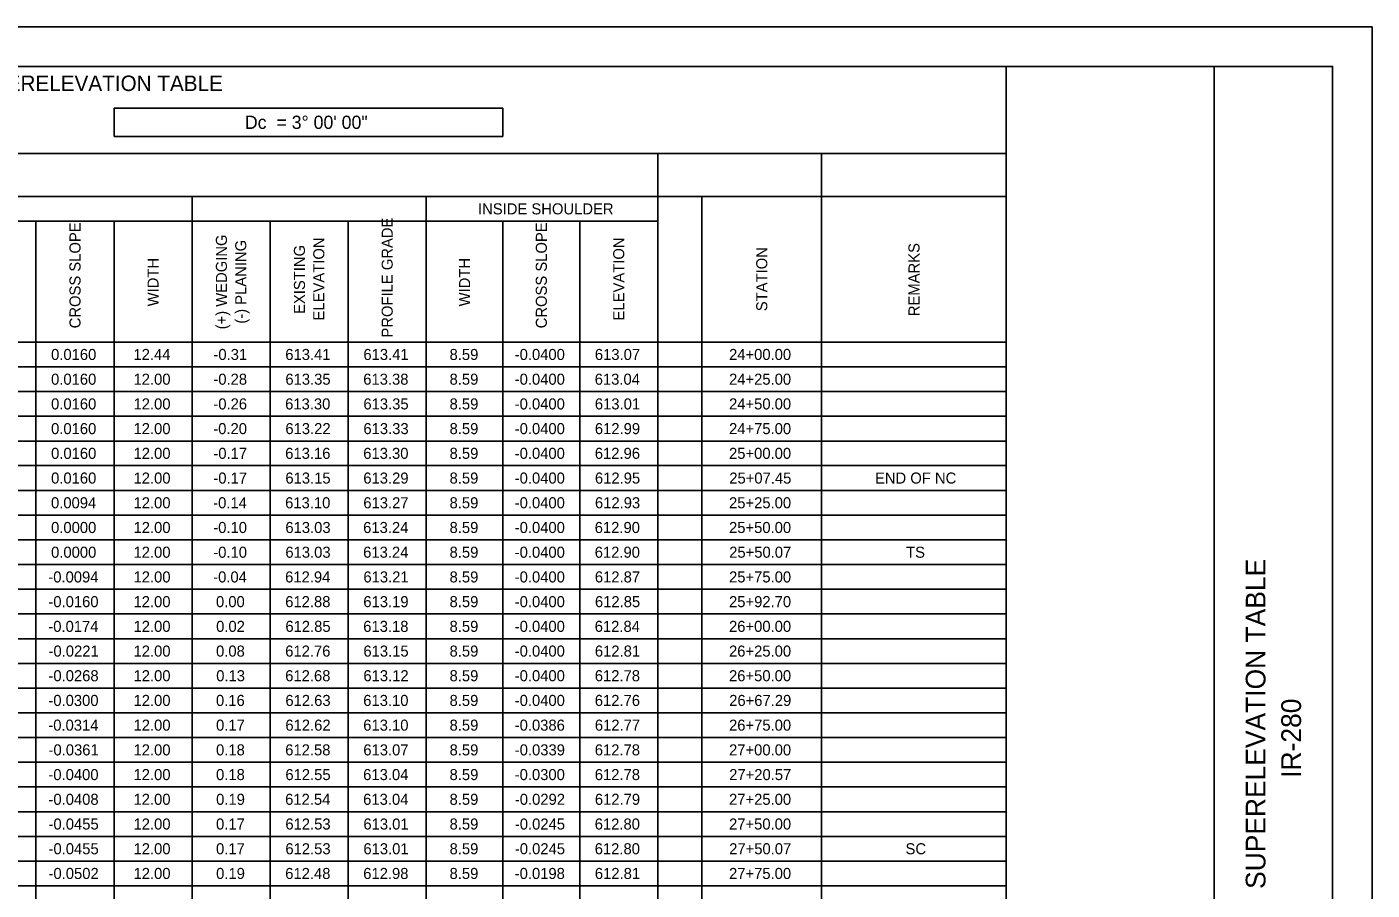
# Model space of a CAD drawing. Extents: x 0 to 34, y 0 to 22.
# Drawn here: x 16.97 to 34, y 11.07 to 22 of the extents above; entities that cross this region are included whole.
import ezdxf

# ---------------------------------------------------------------- set-up
doc = ezdxf.new("R2010")
doc.units = 0
for name, color, linetype in [('SH_Border', 7, 'Continuous'), ('SH_Cut_Line', 7, 'Continuous'), ('SH_Data', 7, 'Continuous'), ('SH_Text', 7, 'Continuous')]:
    doc.layers.add(name, color=color, linetype=linetype)

msp = doc.modelspace()

# ---------------------------------------------------------------- linework, layer by layer
at = {"layer": 'SH_Border'}
msp.add_line((32, 0.5), (32, 21.5), dxfattribs=at)
msp.add_lwpolyline([(1.5, 21.5), (33.5, 21.5), (33.5, 0.5), (1.5, 0.5)], close=True, dxfattribs=at)
at = {"layer": 'SH_Cut_Line'}
msp.add_lwpolyline([(0, 0), (34, 0), (34, 22), (0, 22)], close=True, dxfattribs=at)
at = {"layer": 'SH_Text'}
for p, q in [((5.189, 21.5), (29.368, 21.5)), ((29.368, 21.5), (29.368, 0.484)), ((18.069, 20.973), (22.994, 20.973)), ((18.069, 20.973), (18.069, 20.611)), ((22.994, 20.973), (22.994, 20.611)), ((18.069, 20.611), (22.994, 20.611)), ((4.135, 20.396), (29.368, 20.396)), ((24.954, 20.396), (24.954, 0.484)), ((27.029, 20.396), (27.029, 0.484)), ((4.135, 19.853), (29.368, 19.853)), ((19.057, 19.853), (19.057, 0.484)), ((22.022, 19.853), (22.022, 0.484)), ((25.514, 19.853), (25.514, 0.484)), ((4.135, 19.54), (24.954, 19.54)), ((17.081, 19.54), (17.081, 0.484)), ((18.069, 19.54), (18.069, 0.484)), ((20.046, 19.54), (20.046, 0.484)), ((21.034, 19.54), (21.034, 0.484)), ((22.994, 19.54), (22.994, 0.484)), ((23.966, 19.54), (23.966, 0.484)), ((4.135, 18.008), (29.368, 18.008)), ((4.135, 17.695), (29.368, 17.695)), ((4.135, 17.382), (29.368, 17.382)), ((4.135, 17.069), (29.368, 17.069)), ((4.135, 16.756), (29.368, 16.756)), ((4.135, 16.444), (29.368, 16.444)), ((4.135, 16.131), (29.368, 16.131)), ((4.135, 15.818), (29.368, 15.818)), ((4.135, 15.505), (29.368, 15.505)), ((4.135, 15.192), (29.368, 15.192)), ((4.135, 14.879), (29.368, 14.879)), ((4.135, 14.566), (29.368, 14.566)), ((4.135, 14.253), (29.368, 14.253)), ((4.135, 13.94), (29.368, 13.94)), ((4.135, 13.627), (29.368, 13.627)), ((4.135, 13.314), (29.368, 13.314)), ((4.135, 13.001), (29.368, 13.001)), ((4.135, 12.688), (29.368, 12.688)), ((4.135, 12.375), (29.368, 12.375)), ((4.135, 12.062), (29.368, 12.062)), ((4.135, 11.749), (29.368, 11.749)), ((4.135, 11.436), (29.368, 11.436)), ((4.135, 11.124), (29.368, 11.124))]:
    msp.add_line(p, q, dxfattribs=at)

# ---------------------------------------------------------------- texts
at = {"layer": 'SH_Data'}
for s, p in [('SUPERELEVATION TABLE', (32.65, 11.084)), ('IR-280', (33.1, 12.491))]:
    msp.add_text(s, height=0.25, rotation=90, dxfattribs=at).set_placement(p)
at = {"layer": 'SH_Text'}
for s, height, p in [('WOO/LUC-280-06.20/00.00 - SUPERELEVATION TABLE', 0.196, (12.689, 21.188)), ('Dc  = 3° 00\' 00"', 0.168, (19.726, 20.708)), ('INSIDE SHOULDER', 0.14, (22.678, 19.626)), ('0.0160', 0.14, (17.272, 17.782)), ('12.44', 0.14, (18.315, 17.782)), ('-0.31', 0.14, (19.328, 17.782)), ('613.41', 0.14, (20.238, 17.782)), ('613.41', 0.14, (21.227, 17.782)), ('8.59', 0.14, (22.318, 17.782)), ('-0.0400', 0.14, (23.143, 17.782)), ('613.07', 0.14, (24.158, 17.782)), ('24+00.00', 0.14, (25.857, 17.782)), ('0.0160', 0.14, (17.272, 17.469)), ('12.00', 0.14, (18.316, 17.469)), ('-0.28', 0.14, (19.327, 17.469)), ('613.35', 0.14, (20.239, 17.469)), ('613.38', 0.14, (21.225, 17.469)), ('8.59', 0.14, (22.318, 17.469)), ('-0.0400', 0.14, (23.143, 17.469)), ('613.04', 0.14, (24.156, 17.469)), ('24+25.00', 0.14, (25.857, 17.469)), ('0.0160', 0.14, (17.272, 17.156)), ('12.00', 0.14, (18.316, 17.156)), ('-0.26', 0.14, (19.327, 17.156)), ('613.30', 0.14, (20.236, 17.156)), ('613.35', 0.14, (21.227, 17.156)), ('8.59', 0.14, (22.318, 17.156)), ('-0.0400', 0.14, (23.143, 17.156)), ('613.01', 0.14, (24.158, 17.156)), ('24+50.00', 0.14, (25.857, 17.156)), ('0.0160', 0.14, (17.272, 16.843)), ('12.00', 0.14, (18.316, 16.843)), ('-0.20', 0.14, (19.326, 16.843)), ('613.22', 0.14, (20.239, 16.843)), ('613.33', 0.14, (21.227, 16.843)), ('8.59', 0.14, (22.318, 16.843)), ('-0.0400', 0.14, (23.143, 16.843)), ('612.99', 0.14, (24.158, 16.843)), ('24+75.00', 0.14, (25.857, 16.843)), ('0.0160', 0.14, (17.272, 16.53)), ('12.00', 0.14, (18.316, 16.53)), ('-0.17', 0.14, (19.327, 16.53)), ('613.16', 0.14, (20.237, 16.53)), ('613.30', 0.14, (21.225, 16.53)), ('8.59', 0.14, (22.318, 16.53)), ('-0.0400', 0.14, (23.143, 16.53)), ('612.96', 0.14, (24.157, 16.53)), ('25+00.00', 0.14, (25.857, 16.53)), ('0.0160', 0.14, (17.272, 16.217)), ('12.00', 0.14, (18.316, 16.217)), ('-0.17', 0.14, (19.327, 16.217)), ('613.15', 0.14, (20.239, 16.217)), ('613.29', 0.14, (21.226, 16.217)), ('8.59', 0.14, (22.318, 16.217)), ('-0.0400', 0.14, (23.143, 16.217)), ('612.95', 0.14, (24.159, 16.217)), ('25+07.45', 0.14, (25.86, 16.217)), ('END OF NC', 0.14, (27.705, 16.217)), ('0.0094', 0.14, (17.271, 15.904)), ('12.00', 0.14, (18.316, 15.904)), ('-0.14', 0.14, (19.325, 15.904)), ('613.10', 0.14, (20.236, 15.904)), ('613.27', 0.14, (21.226, 15.904)), ('8.59', 0.14, (22.318, 15.904)), ('-0.0400', 0.14, (23.143, 15.904)), ('612.93', 0.14, (24.159, 15.904)), ('25+25.00', 0.14, (25.857, 15.904)), ('0.0000', 0.14, (17.272, 15.591)), ('12.00', 0.14, (18.316, 15.591)), ('-0.10', 0.14, (19.326, 15.591)), ('613.03', 0.14, (20.239, 15.591)), ('613.24', 0.14, (21.224, 15.591)), ('8.59', 0.14, (22.318, 15.591)), ('-0.0400', 0.14, (23.143, 15.591)), ('612.90', 0.14, (24.156, 15.591)), ('25+50.00', 0.14, (25.857, 15.591)), ('0.0000', 0.14, (17.272, 15.278)), ('12.00', 0.14, (18.316, 15.278)), ('-0.10', 0.14, (19.326, 15.278)), ('613.03', 0.14, (20.239, 15.278)), ('613.24', 0.14, (21.224, 15.278)), ('8.59', 0.14, (22.318, 15.278)), ('-0.0400', 0.14, (23.143, 15.278)), ('612.90', 0.14, (24.156, 15.278)), ('25+50.07', 0.14, (25.859, 15.278)), ('TS', 0.14, (28.099, 15.278)), ('-0.0094', 0.14, (17.237, 14.965)), ('12.00', 0.14, (18.316, 14.965)), ('-0.04', 0.14, (19.325, 14.965)), ('612.94', 0.14, (20.236, 14.965)), ('613.21', 0.14, (21.227, 14.965)), ('8.59', 0.14, (22.318, 14.965)), ('-0.0400', 0.14, (23.143, 14.965)), ('612.87', 0.14, (24.158, 14.965)), ('25+75.00', 0.14, (25.857, 14.965)), ('-0.0160', 0.14, (17.238, 14.652)), ('12.00', 0.14, (18.316, 14.652)), ('0.00', 0.14, (19.36, 14.652)), ('612.88', 0.14, (20.237, 14.652)), ('613.19', 0.14, (21.226, 14.652)), ('8.59', 0.14, (22.318, 14.652)), ('-0.0400', 0.14, (23.143, 14.652)), ('612.85', 0.14, (24.159, 14.652)), ('25+92.70', 0.14, (25.857, 14.652)), ('-0.0174', 0.14, (17.237, 14.339)), ('12.00', 0.14, (18.316, 14.339)), ('0.02', 0.14, (19.362, 14.339)), ('612.85', 0.14, (20.239, 14.339)), ('613.18', 0.14, (21.225, 14.339)), ('8.59', 0.14, (22.318, 14.339)), ('-0.0400', 0.14, (23.143, 14.339)), ('612.84', 0.14, (24.156, 14.339)), ('26+00.00', 0.14, (25.857, 14.339)), ('-0.0221', 0.14, (17.24, 14.026)), ('12.00', 0.14, (18.316, 14.026)), ('0.08', 0.14, (19.361, 14.026)), ('612.76', 0.14, (20.237, 14.026)), ('613.15', 0.14, (21.227, 14.026)), ('8.59', 0.14, (22.318, 14.026)), ('-0.0400', 0.14, (23.143, 14.026)), ('612.81', 0.14, (24.158, 14.026)), ('26+25.00', 0.14, (25.857, 14.026)), ('-0.0268', 0.14, (17.239, 13.714)), ('12.00', 0.14, (18.316, 13.714)), ('0.13', 0.14, (19.363, 13.714)), ('612.68', 0.14, (20.237, 13.714)), ('613.12', 0.14, (21.227, 13.714)), ('8.59', 0.14, (22.318, 13.714)), ('-0.0400', 0.14, (23.143, 13.714)), ('612.78', 0.14, (24.157, 13.714)), ('26+50.00', 0.14, (25.857, 13.714)), ('-0.0300', 0.14, (17.238, 13.401)), ('12.00', 0.14, (18.316, 13.401)), ('0.16', 0.14, (19.36, 13.401)), ('612.63', 0.14, (20.239, 13.401)), ('613.10', 0.14, (21.225, 13.401)), ('8.59', 0.14, (22.318, 13.401)), ('-0.0400', 0.14, (23.143, 13.401)), ('612.76', 0.14, (24.157, 13.401)), ('26+67.29', 0.14, (25.859, 13.401)), ('-0.0314', 0.14, (17.237, 13.088)), ('12.00', 0.14, (18.316, 13.088)), ('0.17', 0.14, (19.361, 13.088)), ('612.62', 0.14, (20.239, 13.088)), ('613.10', 0.14, (21.225, 13.088)), ('8.59', 0.14, (22.318, 13.088)), ('-0.0386', 0.14, (23.143, 13.088)), ('612.77', 0.14, (24.158, 13.088)), ('26+75.00', 0.14, (25.857, 13.088)), ('-0.0361', 0.14, (17.24, 12.775)), ('12.00', 0.14, (18.316, 12.775)), ('0.18', 0.14, (19.361, 12.775)), ('612.58', 0.14, (20.237, 12.775)), ('613.07', 0.14, (21.226, 12.775)), ('8.59', 0.14, (22.318, 12.775)), ('-0.0339', 0.14, (23.144, 12.775)), ('612.78', 0.14, (24.157, 12.775)), ('27+00.00', 0.14, (25.857, 12.775)), ('-0.0400', 0.14, (17.238, 12.462)), ('12.00', 0.14, (18.316, 12.462)), ('0.18', 0.14, (19.361, 12.462)), ('612.55', 0.14, (20.239, 12.462)), ('613.04', 0.14, (21.224, 12.462)), ('8.59', 0.14, (22.318, 12.462)), ('-0.0300', 0.14, (23.143, 12.462)), ('612.78', 0.14, (24.157, 12.462)), ('27+20.57', 0.14, (25.859, 12.462)), ('-0.0408', 0.14, (17.239, 12.149)), ('12.00', 0.14, (18.316, 12.149)), ('0.19', 0.14, (19.362, 12.149)), ('612.54', 0.14, (20.236, 12.149)), ('613.04', 0.14, (21.224, 12.149)), ('8.59', 0.14, (22.318, 12.149)), ('-0.0292', 0.14, (23.145, 12.149)), ('612.79', 0.14, (24.158, 12.149)), ('27+25.00', 0.14, (25.857, 12.149)), ('-0.0455', 0.14, (17.24, 11.836)), ('12.00', 0.14, (18.316, 11.836)), ('0.17', 0.14, (19.361, 11.836)), ('612.53', 0.14, (20.239, 11.836)), ('613.01', 0.14, (21.227, 11.836)), ('8.59', 0.14, (22.318, 11.836)), ('-0.0245', 0.14, (23.145, 11.836)), ('612.80', 0.14, (24.156, 11.836)), ('27+50.00', 0.14, (25.857, 11.836)), ('-0.0455', 0.14, (17.24, 11.523)), ('12.00', 0.14, (18.316, 11.523)), ('0.17', 0.14, (19.361, 11.523)), ('612.53', 0.14, (20.239, 11.523)), ('613.01', 0.14, (21.227, 11.523)), ('8.59', 0.14, (22.318, 11.523)), ('-0.0245', 0.14, (23.145, 11.523)), ('612.80', 0.14, (24.156, 11.523)), ('27+50.07', 0.14, (25.859, 11.523)), ('SC', 0.14, (28.092, 11.523)), ('-0.0502', 0.14, (17.24, 11.21)), ('12.00', 0.14, (18.316, 11.21)), ('0.19', 0.14, (19.362, 11.21)), ('612.48', 0.14, (20.237, 11.21)), ('612.98', 0.14, (21.225, 11.21)), ('8.59', 0.14, (22.318, 11.21)), ('-0.0198', 0.14, (23.143, 11.21)), ('612.81', 0.14, (24.158, 11.21)), ('27+75.00', 0.14, (25.857, 11.21))]:
    msp.add_text(s, height=height, dxfattribs=at).set_placement(p)
for s, p in [('CROSS SLOPE', (17.645, 18.183)), ('PROFILE GRADE', (21.598, 18.066)), ('CROSS SLOPE', (23.55, 18.183)), ('(+) WEDGING', (19.499, 18.17)), ('(-) PLANING', (19.744, 18.242)), ('ELEVATION', (20.732, 18.283)), ('ELEVATION', (24.53, 18.283)), ('REMARKS', (28.269, 18.337)), ('EXISTING ', (20.487, 18.365)), ('STATION', (26.341, 18.4)), ('WIDTH', (18.633, 18.461)), ('WIDTH', (22.578, 18.461))]:
    msp.add_text(s, height=0.14, rotation=90, dxfattribs=at).set_placement(p)

doc.saveas('drawing.dxf')
